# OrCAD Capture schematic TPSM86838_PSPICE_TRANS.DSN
size C; title: TPSM86838 4.5-V to 28-V, 8-A Synchronous Buck Power Module; rev: 1.0; note: Datasheet: SLVSH20         EVM: SLVUCP2; note: Synchronous Step Down Converter; note: with 100mA LDO
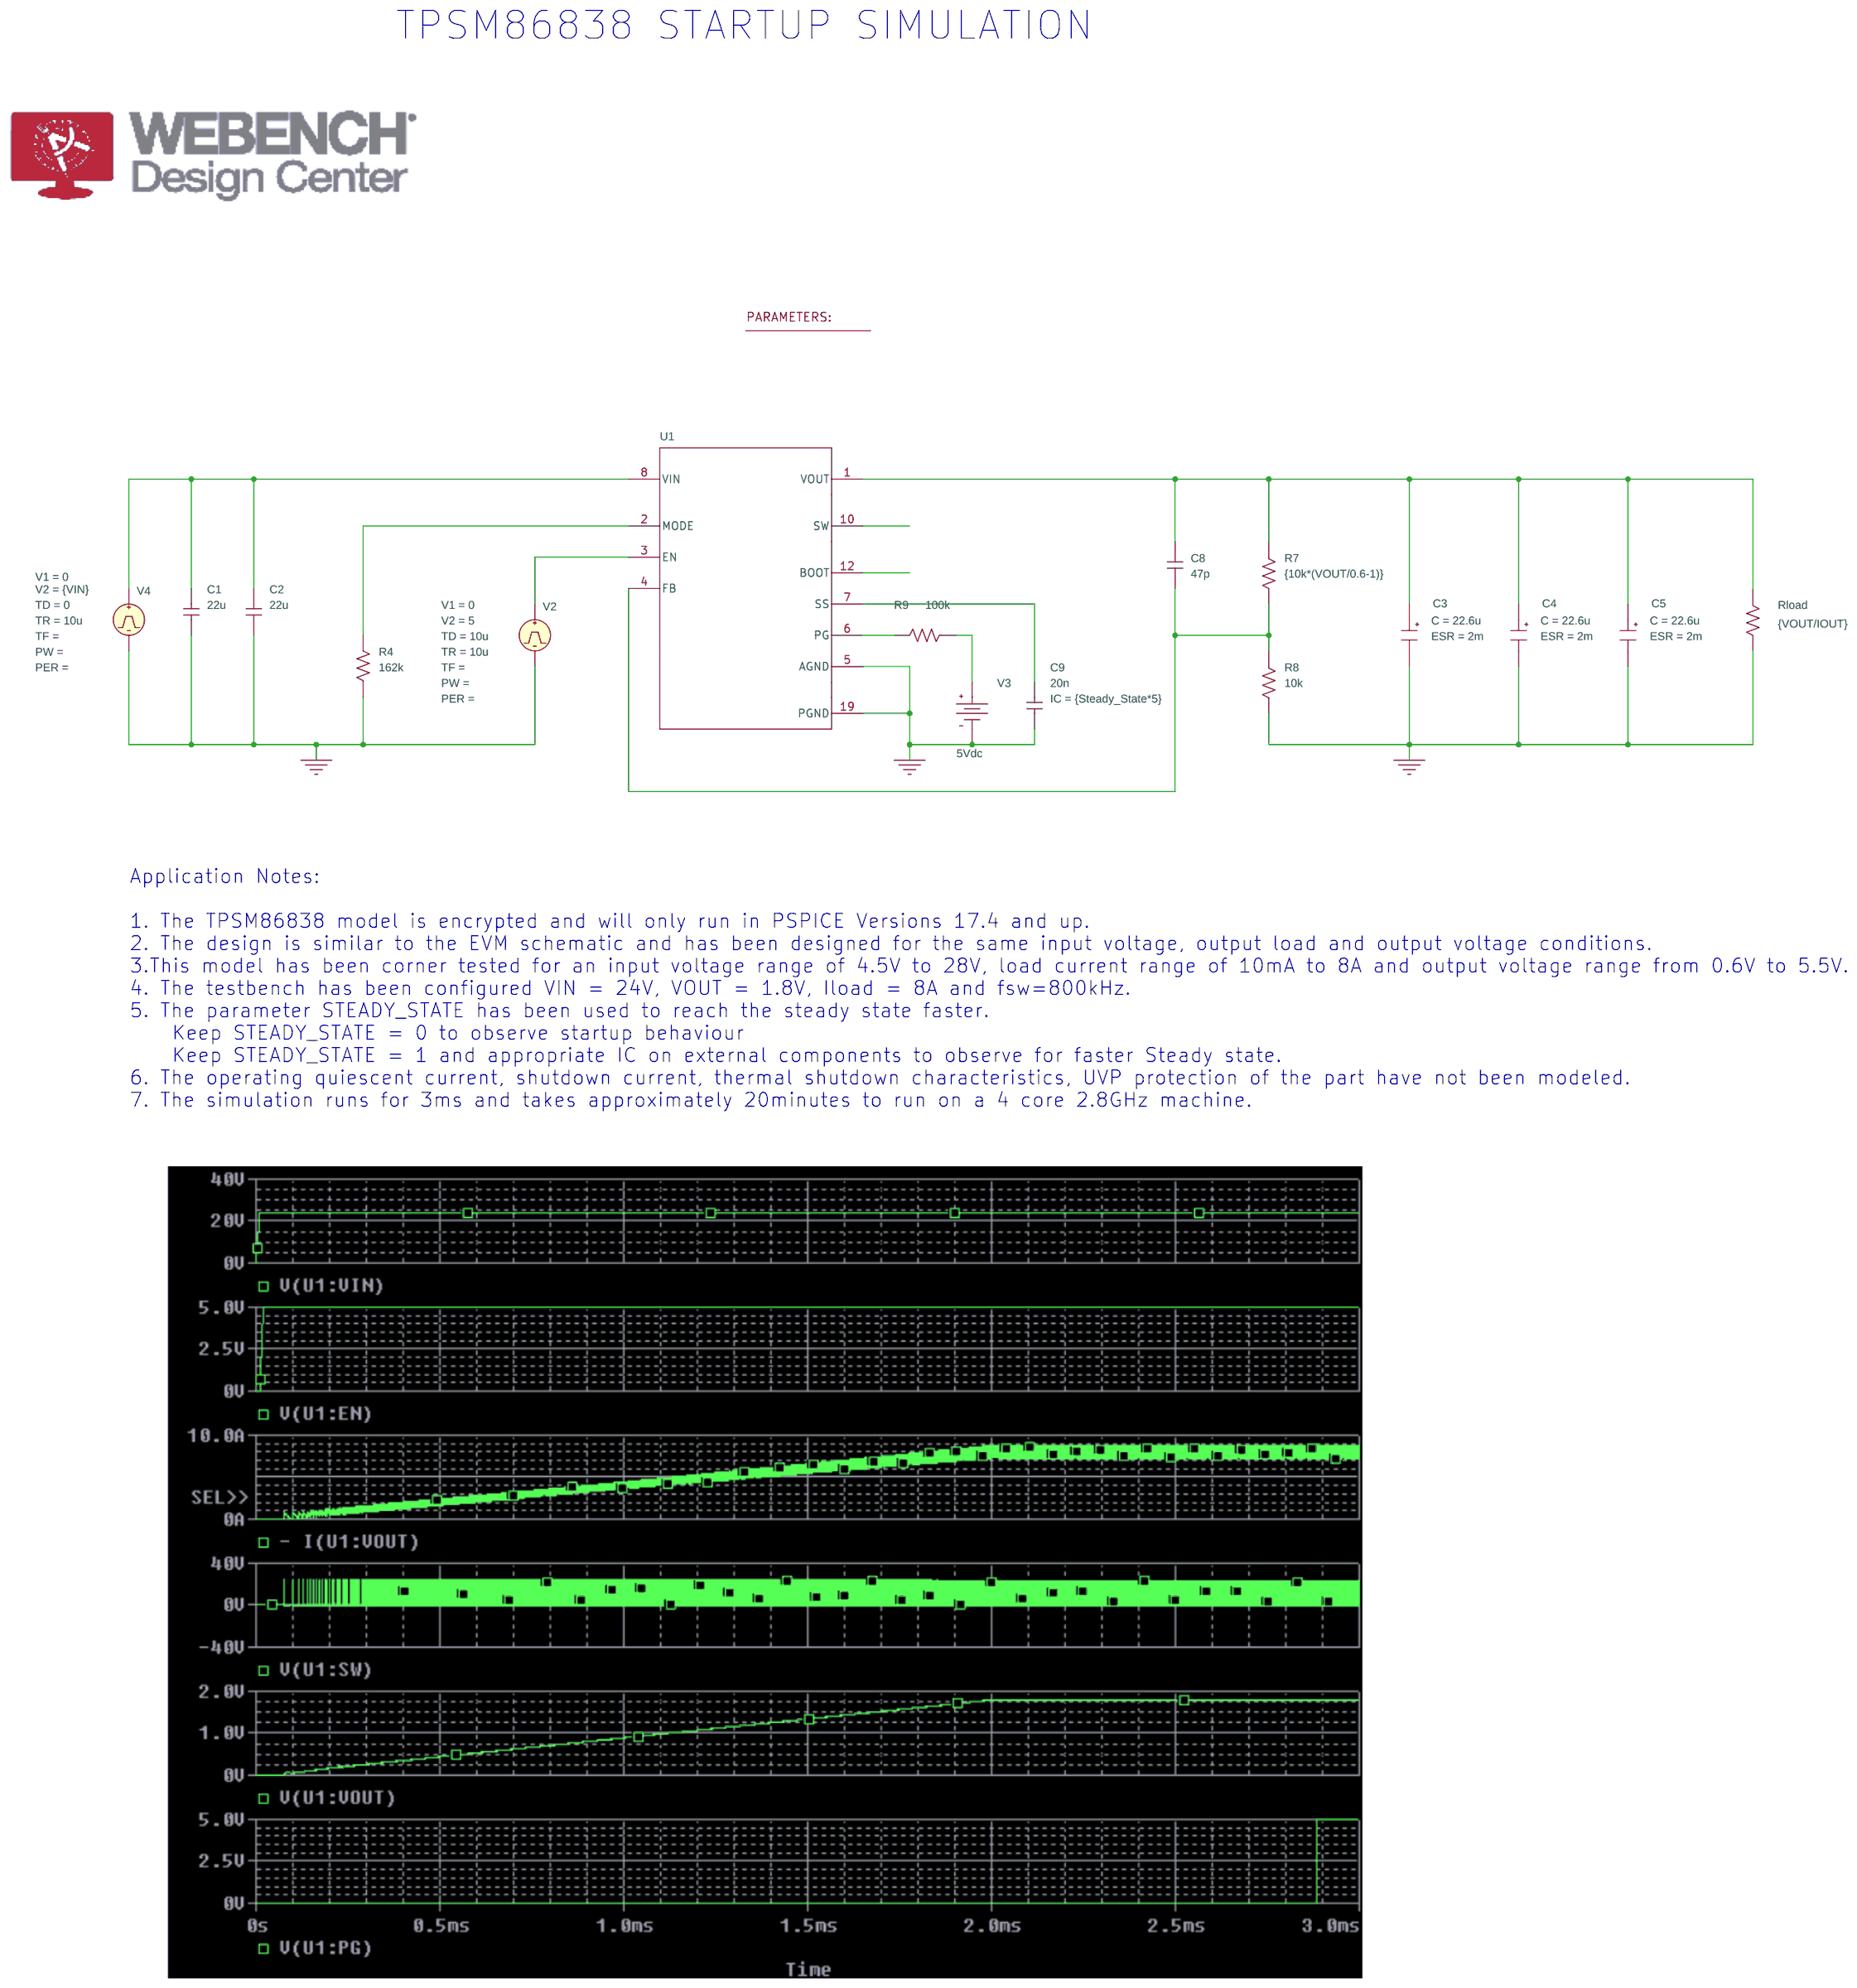
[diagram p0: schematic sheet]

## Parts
3  PARAM
C1  22u  [cap196]
C2  22u  [cap196]
C3  CESR
C4  CESR
C5  CESR
C8  47p  [cap196]
C9  20n  [RAD/CK05]
R4  162k  [AXRC05]
R7  {10k*(VOUT/0.6-1)}  [AX/RC05]
R8  10k  [AX/RC05]
R9  100k  [AXRC05]
Rload  {VOUT/IOUT}  [AX/RC05]
U1  Value  [RCG0019A-MFG]
V2  VPULSE
V3  VDC
V4  VPULSE

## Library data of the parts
3 = PARAM: IOUT: 8; Steady_State: 0; VIN: 24; VOUT: 1.8
C1 C2 C8 = C: IC: 0
C3-C5 = CESR_0: C: 22.6u; ESL: 0; ESR: 2m; IC: 0
C9 = C: IC: {Steady_State*5}
R4 R7-R9 Rload = R
U1 = TPSM86838RCG_TRANS
V2 = VPULSE: TD: 10u; TR: 10u; V1: 0; V2: 5
V3 = VDC: DC: 5Vdc
V4 = VPULSE: TD: 0; TR: 10u; V1: 0; V2: {VIN}

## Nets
0: C1.1 C2.1 C3.2(OUT) C4.2(OUT) C5.2(OUT) C9.2 R4.1 R8.2 Rload.2 U1.5(AGND) U1.19(PGND) V2.2(-) V3.1(-) V4.2(-)
N98789: C1.2 C2.2 U1.8(VIN) V4.1(+)
N98815: C3.1(IN) C4.1(IN) C5.1(IN) C8.2 R7.1 Rload.1 U1.1(VOUT)
N98873: R4.2 U1.2(MODE)
N98889: U1.3(EN) V2.1(+)
N98947: C8.1 R7.2 R8.1 U1.4(FB)
N99033: C9.1 U1.7(SS)
N99235: R9.2 U1.6(PG)
N99241: R9.1 V3.0(+)

Not connected (* = marked no-connect by the designer): U1 10(SW) 12(BOOT)

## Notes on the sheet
- TPSM86838 STARTUP SIMULATION
- Application Notes:
  1. The TPSM86838 model is encrypted and will only run in PSPICE Versions 17.4 and up.
  2. The design is similar to the EVM schematic and has been designed for the same input voltage, output load and output voltage conditions.
  3.This model has been corner tested for an input voltage range of 4.5V to 28V, load current range of 10mA to 8A and output voltage range from 0.6V to 5.5V.
  4. The testbench has been configured VIN = 24V, VOUT = 1.8V, Iload = 8A and fsw=800kHz.
  5. The parameter STEADY_STATE has been used to reach the steady state faster.
      Keep STEADY_STATE = 0 to observe startup behaviour
      Keep STEADY_STATE = 1 and appropriate IC on external components to observe for faster Steady state.
  6. The operating quiescent current, shutdown current, thermal shutdown characteristics, UVP protection of the part have not been modeled.
  7. The simulation runs for 3ms and takes approximately 20minutes to run on a 4 core 2.8GHz machine.
